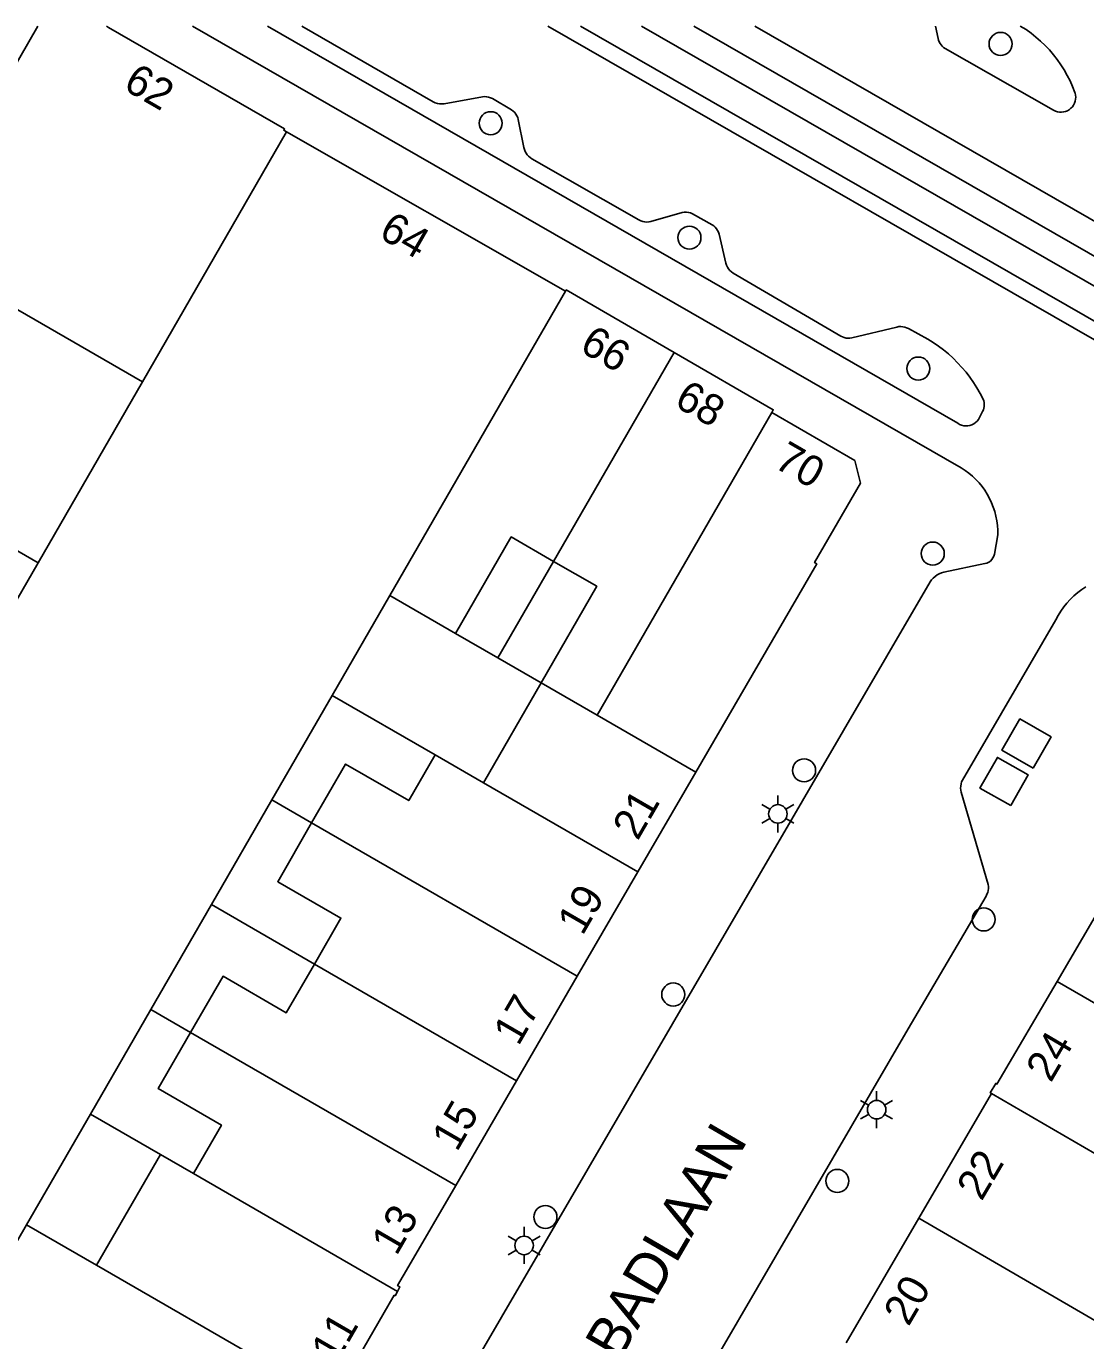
# Model space of a CAD drawing. Extents: x 122462 to 123306, y 485548 to 486417.
# Drawn here: x 122924.9 to 122976.4, y 486353 to 486417 of the extents above; entities that cross this region are included whole.
import ezdxf

# ---------------------------------------------------------------- set-up
doc = ezdxf.new("R2010")
doc.units = 0
for name, color, linetype in [('Level 1', 7, 'Continuous'), ('Level 17', 7, 'Continuous'), ('Level 19', 7, 'Continuous'), ('Level 37', 7, 'Continuous'), ('Level 4', 7, 'Continuous'), ('Level 42', 7, 'Continuous'), ('Level 50', 7, 'Continuous'), ('Level 53', 7, 'Continuous'), ('Level 58', 7, 'Continuous'), ('Level 59', 7, 'Continuous')]:
    doc.layers.add(name, color=color, linetype=linetype)

msp = doc.modelspace()

# ---------------------------------------------------------------- linework, layer by layer
at = {"layer": 'Level 1'}
for p, q in [((122951.099, 486404.087), (122937.539, 486411.819)), ((122930.54, 486399.672), (122925.459, 486390.877)), ((122942.555, 486389.28), (122939.75, 486384.419)), ((122945.752, 486387.435), (122942.555, 486389.28)), ((122947.104, 486380.176), (122949.909, 486385.036)), ((122939.75, 486384.419), (122936.819, 486379.34)), ((122944.756, 486381.531), (122947.104, 486380.176)), ((122954.612, 486375.843), (122957.43, 486380.696)), ((122936.819, 486379.34), (122933.882, 486374.249)), ((122951.666, 486370.772), (122954.612, 486375.843)), ((122933.882, 486374.249), (122930.939, 486369.149)), ((122948.715, 486365.69), (122951.666, 486370.772)), ((122930.939, 486369.149), (122928.002, 486364.059)), ((122945.757, 486360.598), (122948.715, 486365.69)), ((122968.264, 486359.007), (122971.797, 486365.067)), ((122928.002, 486364.059), (122924.897, 486358.678)), ((122928.297, 486356.717), (122931.401, 486362.098)), ((122931.401, 486362.098), (122933.008, 486361.171)), ((122964.734, 486352.951), (122968.264, 486359.007)), ((122924.897, 486358.678), (122928.297, 486356.717))]:
    msp.add_line(p, q, dxfattribs=at)
for points in [[(122925.449, 486416.958), (122919.24, 486406.184), (122930.54, 486399.672)], [(122937.539, 486411.819), (122937.4, 486411.9), (122937.439, 486411.969), (122928.876, 486416.904), (122928.782, 486416.958)], [(122956.38, 486401.098), (122951.13, 486404.14), (122951.099, 486404.087)], [(122961.116, 486398.182), (122961.189, 486398.309), (122956.38, 486401.098)], [(122957.43, 486380.696), (122963.309, 486390.819), (122963.2, 486390.884), (122965.439, 486394.739), (122965.16, 486395.84), (122961.116, 486398.182)], [(122925.459, 486390.877), (122914.105, 486397.437), (122900.278, 486373.504)], [(122950.518, 486390.94), (122948.459, 486392.128), (122945.752, 486387.435)], [(122949.909, 486385.036), (122952.617, 486389.729), (122950.518, 486390.94)], [(122974.988, 486370.518), (122983.394, 486384.877), (122983.308, 486384.928), (122983.59, 486385.41), (122984.075, 486385.128), (122984.025, 486385.043), (122989.347, 486381.946), (122989.397, 486382.031), (122989.638, 486381.89)], [(122938.754, 486378.224), (122940.404, 486381.082), (122943.475, 486379.31), (122944.756, 486381.531)], [(122938.888, 486371.36), (122940.177, 486373.593), (122937.105, 486375.366), (122938.754, 486378.224)], [(122932.873, 486368.033), (122934.449, 486370.764), (122937.521, 486368.991), (122938.888, 486371.36)], [(122971.797, 486365.067), (122971.739, 486365.1), (122972.008, 486365.556), (122972.064, 486365.523), (122974.988, 486370.518)], [(122933.008, 486361.171), (122934.37, 486363.53), (122931.298, 486365.303), (122932.873, 486368.033)], [(122942.93, 486355.445), (122943.049, 486355.66), (122942.93, 486355.73), (122943.479, 486356.675), (122945.757, 486360.598)], [(122939.778, 486350.092), (122942.767, 486355.255), (122942.809, 486355.229), (122942.93, 486355.445)]]:
    msp.add_lwpolyline(points, dxfattribs=at)
at = {"layer": 'Level 17'}
for points in [[(122932.969, 486416.958), (122970.322, 486395.489), (122970.514, 486395.365), (122970.698, 486395.229), (122970.873, 486395.082), (122971.039, 486394.925), (122971.195, 486394.757), (122971.34, 486394.58), (122971.473, 486394.395), (122971.595, 486394.202), (122971.705, 486394.001), (122971.802, 486393.794), (122971.887, 486393.582), (122971.957, 486393.364), (122972.015, 486393.143), (122972.058, 486392.918), (122972.087, 486392.692), (122972.103, 486392.464), (122972.104, 486392.235), (122971.947, 486391.286), (122971.918, 486391.193), (122971.873, 486391.105), (122971.816, 486391.026), (122971.746, 486390.958), (122971.666, 486390.901), (122971.578, 486390.859), (122971.484, 486390.831), (122969.487, 486390.414), (122969.372, 486390.383), (122969.261, 486390.338), (122969.156, 486390.28), (122969.059, 486390.21), (122968.971, 486390.129), (122968.893, 486390.038), (122968.827, 486389.938), (122947.99, 486354.186), (122925.615, 486315.795)], [(122936.615, 486416.958), (122970.166, 486397.655), (122970.254, 486397.603), (122970.349, 486397.564), (122970.449, 486397.539), (122970.551, 486397.528)], [(122971.431, 486398.389), (122971.447, 486398.478), (122971.45, 486398.569), (122971.442, 486398.659), (122971.422, 486398.748), (122971.391, 486398.833), (122971.249, 486399.108), (122971.095, 486399.375), (122970.929, 486399.636), (122970.752, 486399.89), (122970.564, 486400.135), (122970.365, 486400.372), (122970.156, 486400.599), (122969.937, 486400.817), (122969.709, 486401.026), (122969.471, 486401.224), (122969.225, 486401.411), (122968.971, 486401.587), (122968.71, 486401.752), (122967.766, 486402.262), (122967.677, 486402.303), (122967.584, 486402.333), (122967.488, 486402.351), (122967.391, 486402.358), (122967.293, 486402.353), (122967.197, 486402.336), (122965.006, 486401.806), (122964.916, 486401.793), (122964.825, 486401.792), (122964.734, 486401.801), (122964.645, 486401.821), (122964.559, 486401.853), (122964.478, 486401.894), (122959.245, 486404.961), (122959.162, 486405.018), (122959.087, 486405.085), (122959.022, 486405.162), (122958.967, 486405.247), (122958.925, 486405.339), (122958.895, 486405.435), (122958.56, 486406.853), (122958.531, 486406.945), (122958.49, 486407.032), (122958.438, 486407.113), (122958.375, 486407.185), (122958.302, 486407.249), (122958.222, 486407.302), (122957.274, 486407.836), (122957.178, 486407.881), (122957.077, 486407.911), (122956.972, 486407.926), (122956.866, 486407.924), (122956.762, 486407.907), (122955.246, 486407.471), (122955.148, 486407.45), (122955.049, 486407.442), (122954.949, 486407.447), (122954.851, 486407.466), (122954.757, 486407.497), (122954.667, 486407.541), (122949.457, 486410.521), (122949.375, 486410.575), (122949.301, 486410.638), (122949.235, 486410.71), (122949.177, 486410.789), (122949.13, 486410.875), (122949.094, 486410.966), (122949.069, 486411.06), (122948.801, 486412.424), (122948.775, 486412.519), (122948.736, 486412.609), (122948.686, 486412.692), (122948.624, 486412.768), (122948.552, 486412.835), (122948.471, 486412.891), (122947.544, 486413.439), (122947.455, 486413.484), (122947.36, 486413.515), (122947.262, 486413.533), (122947.162, 486413.537), (122947.063, 486413.526), (122945.205, 486413.192), (122945.094, 486413.18), (122944.982, 486413.183), (122944.871, 486413.203), (122944.765, 486413.237), (122944.664, 486413.286), (122938.272, 486416.958)], [(122950.231, 486416.958), (122979.779, 486400.007), (122980.01, 486400.414), (122981.72, 486399.435), (122981.475, 486398.962), (123013.204, 486380.779), (123042.881, 486363.771)], [(122969.076, 486416.958), (122969.215, 486416.367), (122969.232, 486416.281), (122969.261, 486416.199), (122969.301, 486416.121), (122969.35, 486416.049), (122969.409, 486415.984), (122969.476, 486415.928), (122969.55, 486415.881), (122974.82, 486412.873), (122974.911, 486412.829), (122975.007, 486412.799), (122975.107, 486412.782), (122975.208, 486412.779)], [(122975.208, 486412.779), (122975.308, 486412.791), (122975.406, 486412.816), (122975.499, 486412.855), (122975.586, 486412.906), (122975.665, 486412.969), (122975.734, 486413.043), (122975.792, 486413.125), (122975.838, 486413.215), (122975.871, 486413.31), (122975.891, 486413.409), (122975.896, 486413.51), (122975.888, 486413.611), (122975.865, 486413.709), (122975.854, 486413.743), (122975.744, 486414.025), (122975.621, 486414.301), (122975.485, 486414.571), (122975.335, 486414.835), (122975.173, 486415.09), (122974.999, 486415.338), (122974.814, 486415.577), (122974.617, 486415.806), (122974.409, 486416.026), (122974.191, 486416.236), (122973.963, 486416.435), (122973.725, 486416.622), (122973.479, 486416.798), (122973.2, 486416.958)], [(122970.551, 486397.528), (122970.654, 486397.532), (122970.755, 486397.551), (122970.852, 486397.584), (122970.943, 486397.631), (122971.027, 486397.69), (122971.102, 486397.761), (122971.165, 486397.842), (122971.367, 486398.22), (122971.405, 486398.302), (122971.431, 486398.389)], [(122976.391, 486389.698), (122976.187, 486389.565), (122975.992, 486389.419), (122975.807, 486389.262), (122975.631, 486389.093), (122975.467, 486388.913), (122975.315, 486388.723), (122975.175, 486388.524), (122975.048, 486388.316), (122974.934, 486388.101), (122970.393, 486380.305), (122970.35, 486380.213), (122970.32, 486380.116), (122970.303, 486380.017), (122970.299, 486379.916), (122970.308, 486379.815), (122970.331, 486379.716), (122971.644, 486375.233), (122971.656, 486375.135), (122971.656, 486375.037), (122971.643, 486374.939), (122971.619, 486374.844), (122971.582, 486374.752)], [(122971.582, 486374.752), (122971.535, 486374.666), (122967.757, 486368.219), (122956.772, 486349.34)]]:
    msp.add_lwpolyline(points, dxfattribs=at)
at = {"layer": 'Level 19'}
for p, q in [((122950.518, 486390.94), (122947.81, 486386.247)), ((122947.81, 486386.247), (122945.752, 486387.435)), ((122949.909, 486385.036), (122947.81, 486386.247)), ((122944.756, 486381.531), (122939.75, 486384.419)), ((122938.754, 486378.224), (122936.819, 486379.34)), ((122938.888, 486371.36), (122933.882, 486374.249)), ((122932.873, 486368.033), (122930.939, 486369.149)), ((122931.401, 486362.098), (122928.002, 486364.059))]:
    msp.add_line(p, q, dxfattribs=at)
at = {"layer": 'Level 37'}
for points in [[(122951.816, 486416.958), (123052.678, 486359.058)], [(122954.79, 486416.958), (123053.415, 486360.342)], [(123054.664, 486361.047), (122957.327, 486416.958)], [(123055.402, 486362.33), (122960.298, 486416.958)]]:
    msp.add_lwpolyline(points, dxfattribs=at)
at = {"layer": 'Level 4'}
for p, q in [((122937.539, 486411.819), (122930.54, 486399.672)), ((122942.555, 486389.28), (122951.099, 486404.087)), ((122950.518, 486390.94), (122956.38, 486401.098)), ((122952.626, 486383.469), (122961.116, 486398.182)), ((122925.459, 486390.877), (122920.282, 486381.917)), ((122952.626, 486383.469), (122949.909, 486385.036)), ((122957.43, 486380.696), (122952.626, 486383.469)), ((122954.612, 486375.843), (122947.104, 486380.176)), ((122951.666, 486370.772), (122938.754, 486378.224)), ((122948.715, 486365.69), (122938.888, 486371.36)), ((122980.954, 486367.048), (122974.988, 486370.518)), ((122945.757, 486360.598), (122932.873, 486368.033)), ((122981.438, 486359.459), (122971.797, 486365.067)), ((122942.93, 486355.445), (122933.008, 486361.171)), ((122980.712, 486351.767), (122968.264, 486359.007)), ((122924.897, 486358.678), (122918.913, 486348.308)), ((122939.778, 486350.092), (122928.297, 486356.717))]:
    msp.add_line(p, q, dxfattribs=at)
at = {"layer": 'Level 42'}
for points in [[(122973.821, 486380.888), (122972.302, 486381.765), (122973.179, 486383.284), (122974.698, 486382.407), (122973.821, 486380.888)], [(122972.734, 486379.064), (122971.237, 486379.915), (122972.088, 486381.412), (122973.585, 486380.561), (122972.734, 486379.064)]]:
    msp.add_lwpolyline(points, dxfattribs=at)
at = {"layer": 'Level 50'}
for p, q in [((122961.419, 486379.111), (122961.419, 486379.561)), ((122961.029, 486378.886), (122960.639, 486379.111)), ((122962.198, 486379.111), (122961.808, 486378.886)), ((122961.029, 486378.436), (122960.639, 486378.211)), ((122961.419, 486377.761), (122961.419, 486378.211)), ((122962.198, 486378.211), (122961.808, 486378.436)), ((122965.827, 486364.503), (122965.437, 486364.728)), ((122966.217, 486364.728), (122966.217, 486365.178)), ((122966.996, 486364.728), (122966.606, 486364.503)), ((122965.827, 486364.053), (122965.437, 486363.828)), ((122966.217, 486363.378), (122966.217, 486363.828)), ((122966.996, 486363.828), (122966.606, 486364.053)), ((122949.083, 486358.13), (122949.083, 486358.58)), ((122948.693, 486357.905), (122948.303, 486358.13)), ((122949.862, 486358.13), (122949.472, 486357.905)), ((122948.693, 486357.455), (122948.303, 486357.23)), ((122949.083, 486356.78), (122949.083, 486357.23)), ((122949.862, 486357.23), (122949.472, 486357.455))]:
    msp.add_line(p, q, dxfattribs=at)
for centre in [(122961.419, 486378.661), (122966.217, 486364.278), (122949.083, 486357.68)]:
    msp.add_circle(centre, 0.45, dxfattribs=at)
at = {"layer": 'Level 53'}
for centre in [(122972.243, 486416.1), (122947.459, 486412.246), (122957.12, 486406.682), (122968.243, 486400.317), (122968.946, 486391.318), (122962.69, 486380.778), (122971.422, 486373.53), (122956.331, 486369.881), (122964.308, 486360.816), (122950.118, 486359.062)]:
    msp.add_circle(centre, 0.56, dxfattribs=at)

# ---------------------------------------------------------------- texts
at = {"layer": 'Level 58'}
for s, rotation, p in [('62', 330.04426, (122929.538, 486413.929)), ('64', 330.04426, (122941.956, 486406.719)), ('66', 330.04426, (122951.72, 486401.195)), ('68', 330.04426, (122956.318, 486398.53)), ('70', 330.04426, (122961.166, 486395.551)), ('21', 59.93901, (122954.604, 486377.321)), ('19', 59.93901, (122951.92, 486372.699)), ('17', 59.93901, (122948.805, 486367.335)), ('24', 59.51267, (122974.685, 486365.554)), ('15', 59.93901, (122945.817, 486362.189)), ('22', 59.51267, (122971.321, 486359.795)), ('13', 59.93901, (122942.879, 486357.132)), ('20', 59.51267, (122967.767, 486353.698)), ('11', 59.93901, (122939.952, 486351.887))]:
    msp.add_text(s, height=1.5, rotation=rotation, dxfattribs=at).set_placement(p)
at = {"layer": 'Level 59'}
msp.add_text('PLANTAGE BADLAAN', height=2, rotation=59.78895, dxfattribs=at).set_placement((122946.139, 486339.024))

doc.saveas('drawing.dxf')
